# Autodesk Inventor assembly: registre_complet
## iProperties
Author: chr
Created: 2001-06
Part Number: registre_complet
Document SubType Name: Assemblage
Designer: chr
Control State: 0
Master: False
Checked Out: False
PropertySet Name: Design Tracking Control
Shininess: 21.0
Length Units: 11269
Angle Units: 11286
Time Units: 11279
Mass Units: 11290
Length Display Precision: 3
Angle Display Precision: 2
Compacted: False
PropertySet Name: _Private Model Information
Density: 0.0
Volumn: 0.0
Area: 0.0
PropertySet Name: Model Information
